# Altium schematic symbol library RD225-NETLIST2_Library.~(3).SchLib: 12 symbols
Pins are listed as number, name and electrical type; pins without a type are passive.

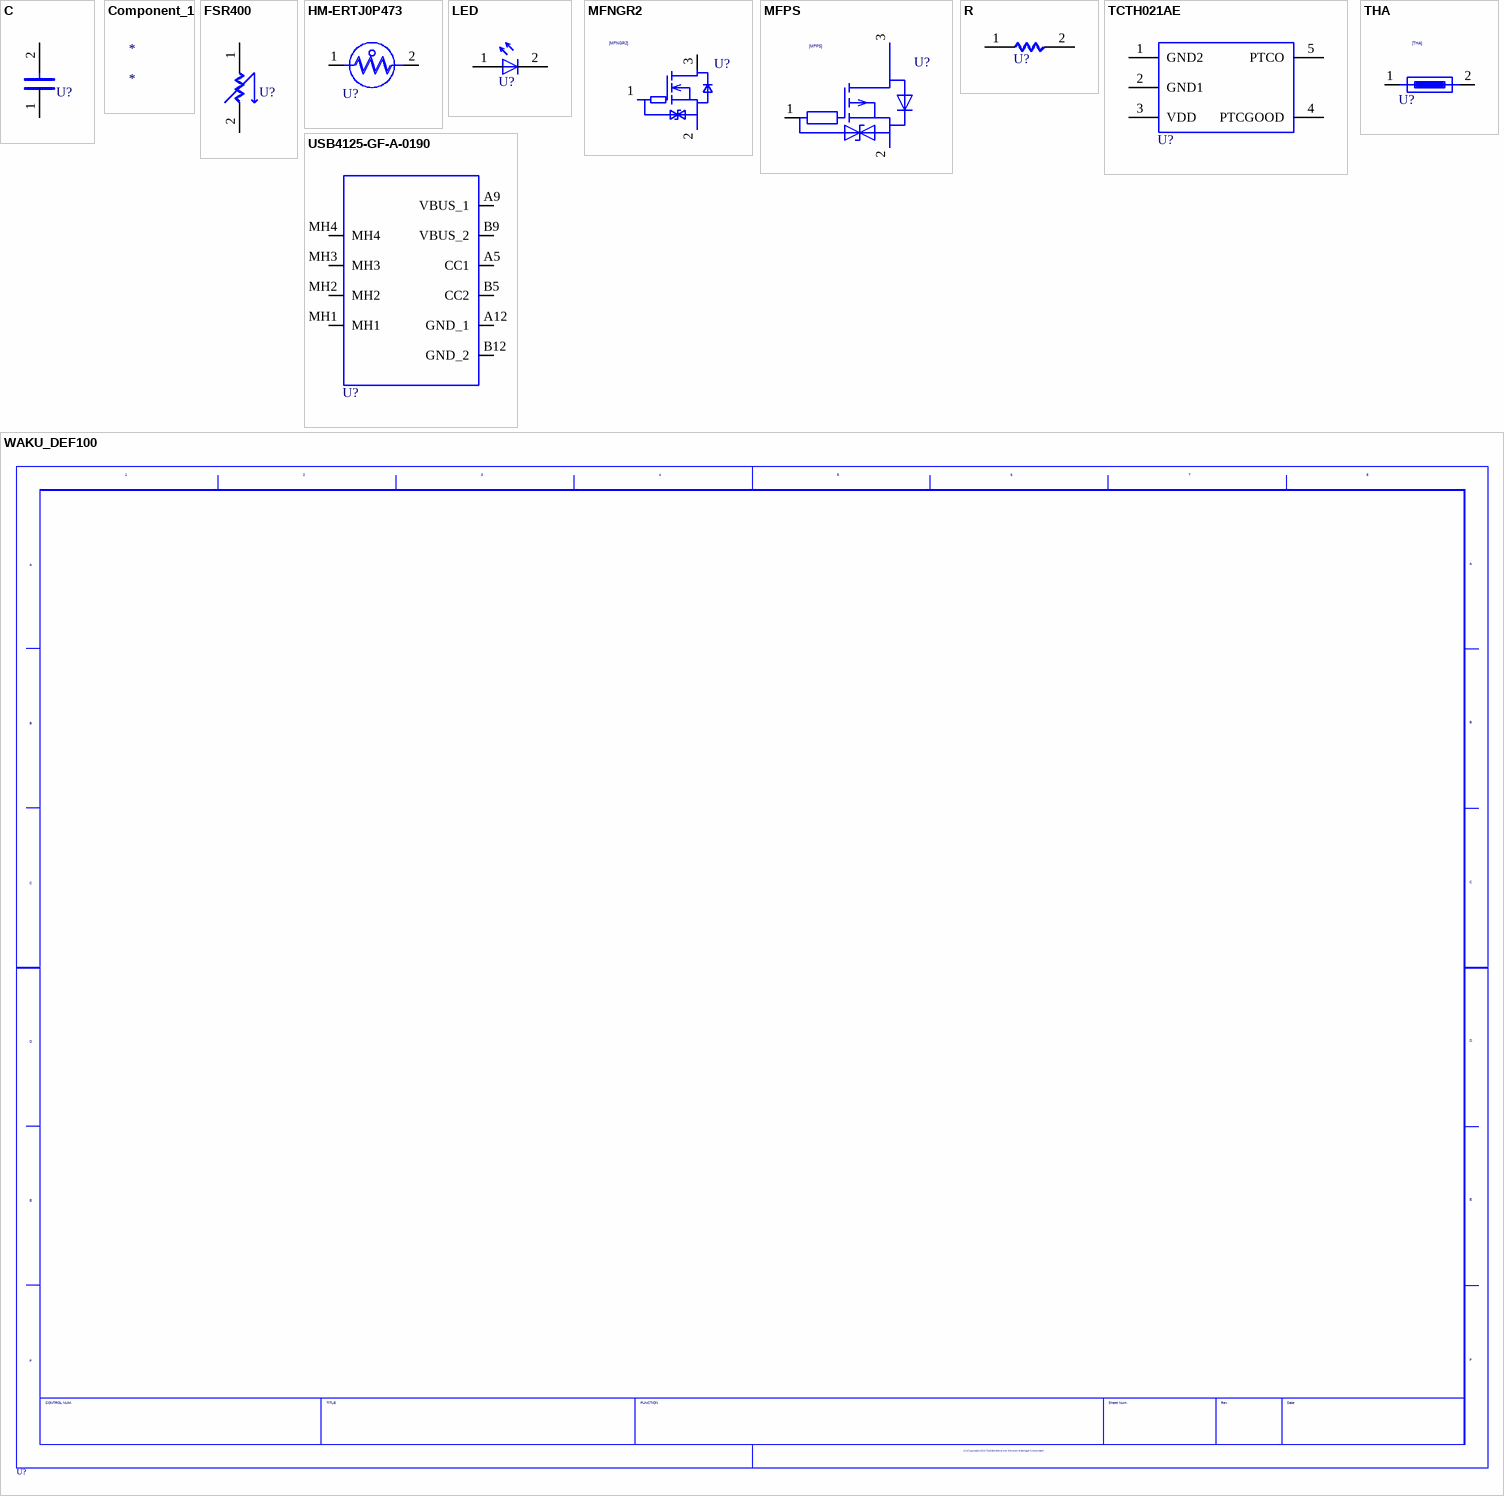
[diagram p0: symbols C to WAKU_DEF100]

## C
designator U?  (value not drawn)
OriginalSymbolOrigin: (2540,7620); Altium-Right: 20; Altium-Bottom: 10
pins: 1, 2

## Component_1
designator *

## FSR400
designator U?  (value not drawn)
SAVEAREA0: -12454,-13119,45493,18589; TIME: 12:32:26; UPDATEUSER: t5459927; SAVECOUNT: 1; OriginalSymbolOrigin: (10160,12700); Altium-Right: 30; Altium-Bottom: 20
pins: 1, 2

## HM-ERTJ0P473
designator U?  (value not drawn)
CDBNAME: R; MONOCODE: E00000368; DEVICENAME: ERTJ0EP473H; SAVECOUNT: 7; SAVEAREA0: -34062,-18143,50567,39798; TIME: 17:24:52; UPDATEUSER: Administrator; UPDATETIME: 15:47:22; OriginalSymbolOrigin: (2540,5080); Altium-Right: 40
pins: 1 (io), 2 (io)

## LED
designator U?  (value not drawn)
SAVEAREA0: -6799,-183,19247,15664; TIME: 14:49:55; UPDATEUSER: fukuda-y; UPDATETIME: 13:54:07; SAVECOUNT: 4; OriginalSymbolOrigin: (5080,7620); Altium-Right: 10; Altium-Bottom: 30
pins: 1 A, 2 C

## MFNGR2
designator U?  (value not drawn)
SAVECOUNT: 25; SAVEAREA0: -9479,-3469,21984,16316; TIME: 16:49:03; UPDATEUSER: tomizawa-y; UPDATETIME: 16:24:51; OriginalSymbolOrigin: (0,10160); Altium-Right: 50; Altium-Bottom: 40
pins: 1 G, 2 S, 3 D

## MFPS
designator U?  (value not drawn)
SAVECOUNT: 24; SAVEAREA0: -2907,-251,25408,18358; TIME: 08:01:03; UPDATEUSER: sato-yr; UPDATETIME: 15:10:02; OriginalSymbolOrigin: (2540,17780); Altium-Right: 80; Altium-Bottom: 70
pins: 1 G, 2 S, 3 D

## R
designator U?  (value not drawn)
OriginalSymbolOrigin: (5080,5080); Altium-Right: 20
pins: 1, 2

## TCTH021AE
designator U?  (value not drawn)
SAVEAREA0: -21868,-8311,47688,23382; TIME: 17:28:34; UPDATEUSER: PS4_common_PC; UPDATETIME: 17:38:33; SAVECOUNT: 2; OriginalSymbolOrigin: (5080,15240); Altium-Right: 90; Altium-Bottom: 60
pins: 1 GND2, 2 GND1, 3 VDD, 4 PTCGOOD, 5 PTCO

## THA
designator U?  (value not drawn)
SAVECOUNT: 3; SAVEAREA0: -562,-143,15615,10489; TIME: 16:37:29; UPDATEUSER: sato-yr; OriginalSymbolOrigin: (2540,5080); Altium-Right: 40; Altium-Bottom: 20
pins: 1, 2

## USB4125-GF-A-0190
designator U?  (value not drawn)
TIME: 13:15:33; UPDATEUSER: t5459927; UPDATETIME: 17:07:21; SAVECOUNT: 7; SAVEAREA0: -96519,-35138,112864,60268; OriginalSymbolOrigin: (0,35560); Altium-Right: 90; Altium-Bottom: 140
pins: A5 CC1, A9 VBUS_1, A12 GND_1, B5 CC2, B9 VBUS_2, B12 GND_2, MH1, MH2, MH3, MH4

## WAKU_DEF100
designator U?  (value not drawn)
PLOTTIME: HH:MM; SAVEAREA0: 186441,-70995,448301,50770; TIME: 14:30:25; UPDATEUSER: t5459927; UPDATETIME: 09:09:51; SAVECOUNT: 8; OriginalSymbolOrigin: (10160,284480); Altium-Right: 1570; Altium-Bottom: 1070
